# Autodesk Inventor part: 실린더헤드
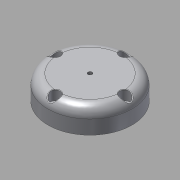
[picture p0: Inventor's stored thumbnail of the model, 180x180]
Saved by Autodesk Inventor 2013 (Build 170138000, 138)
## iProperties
Created: 2016-11
Part Number: 실린더헤드
Material: 알루미늄 6061
Document SubType Name: Modeling
Designer: mduedu
Density: 2.71 g/cm^3
Mass: 284.819 g
Surface Area: 227.25 cm^2
Volume: 105.099 cm^3
Author: mduedu
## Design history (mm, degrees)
sketch "스케치1"
  geometry: C1 r 42 at (0, 0); 1 further point
  constraints: 1 centre point, 1 coincident
  dimensions: "d0" = 84 diameter of C1
extrude "돌출1" new body sketch "스케치1" distance "d1" = 24; taper "d2" = 0 deg
fillet "모깎기1" dims "d3" = 10
sketch "스케치2"
  geometry: C1 r 30 at (0, 0); 1 further point
  constraints: 1 centre point, 1 coincident
  dimensions: "d4" = 60 diameter of C1
extrude "돌출2" join sketch "스케치2" distance "d5" = 5; taper "d6" = 0 deg
sketch "스케치3"
  geometry: C1 r 25 at (0, 0); 1 further point
  constraints: 1 centre point, 1 coincident
  dimensions: "d7" = 50 diameter of C1
extrude "돌출3" cut sketch "스케치3" distance "d8" = 20; taper "d9" = 0 deg
hole "구멍1" diameter "d12" = 4.134; stored, may be unused: countersink angle "d16" = 90 deg, drill point angle "d18" = 118 deg; dims "d10" = 10, "d11" = 10, "d13" = 6, "d14" = 4, "d15" = 2, "d17" = 8
chamfer "모따기1" distance "d19" = 1; stored, may be unused: second distance "d20" = 2, angle "d21" = 45 deg
fillet "모깎기2" dims "d22" = 3
sketch "스케치4"
  geometry: C1 r 17.5 at (0, 0); 1 further point
  constraints: 1 centre point, 1 coincident
  dimensions: "d23" = 35 diameter of C1
extrude "돌출4" cut sketch "스케치4" distance "d24" = 2; taper "d25" = 0 deg
fillet "모깎기3" dims "d26" = 0.5
sketch "스케치5" dims "d32" = 70
  geometry: C1 r 5 at (0, 35); 3 further points
  constraints: 2 coincident, 2 vertical alignment, 1 centre point, 2 other
  dimensions: "d33" = 10 diameter of C1
extrude "돌출5" cut sketch "스케치5" distance "d34" = 10; taper "d35" = 0 deg
sketch "스케치6" dims "d39" = 70
  geometry: 6 further points
  constraints: 2 vertical alignment, 1 coincident, 7 other
  dimensions: "d42" = 360 deg dimension on point (0, -35) point (0, 0) (derived)
sketch "스케치7"
  geometry: 4 further points
  constraints: 4 other
hole "구멍2" sketch "스케치7" at (0, 70), (-35, 35), (35, 35), (0, 0) diameter "d44" = 5.5; stored, may be unused: countersink angle "d48" = 90 deg, drill point angle "d50" = 0 deg; dims "d45" = 6, "d46" = 4, "d47" = 2, "d49" = 8
fillet "모깎기4" dims "d51" = 0.5
chamfer "모따기2" distance "d54" = 5; stored, may be unused: second distance "d55" = 2, angle "d56" = 30 deg
node "솔리드1"
pattern_circular "원형 패턴1" dims angle "d37" = 360 deg
